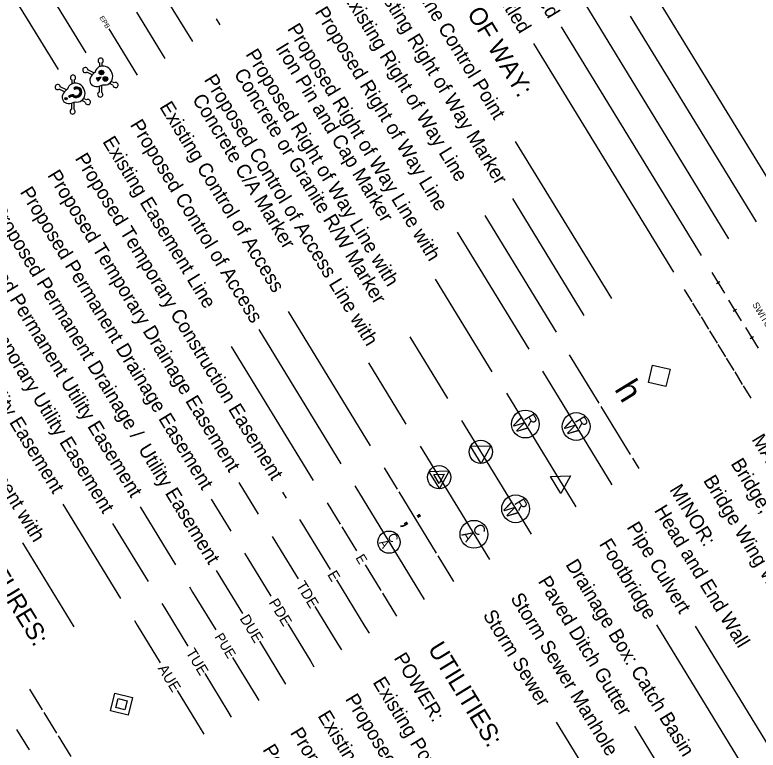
# Model space of a CAD drawing. Extents: x 1750583 to 1791140, y 783580 to 827376.
# Drawn here: x 1782646 to 1783106.5, y 784461.2 to 784917 of the extents above; entities that cross this region are included whole.
import ezdxf

# ---------------------------------------------------------------- set-up
doc = ezdxf.new("R2010")
doc.units = 0
for name, color, linetype in [('Prop Dimension Text', 7, 'Continuous'), ('Prop Easement Permanent Drainage Utility', 7, 'Continuous'), ('Prop ROW Permanent Easement CELL', 7, 'Continuous'), ('Sheet Symbology CELL', 7, 'Continuous')]:
    doc.layers.add(name, color=color, linetype=linetype)

msp = doc.modelspace()

# ---------------------------------------------------------------- linework, layer by layer
at = {"layer": 'Prop Dimension Text'}
msp.add_lwpolyline([(1783041.18, 784699.91), (1783051.94, 784697.31), (1783049.34, 784686.56), (1783038.59, 784689.15)], close=True, dxfattribs=at)
at = {"layer": 'Prop Easement Permanent Drainage Utility'}
for p, q in [((1782770.72, 784572.53), (1782787.04, 784545.82)), ((1782797.47, 784528.76), (1782813.74, 784502.13))]:
    msp.add_line(p, q, dxfattribs=at)
at = {"layer": 'Prop ROW Permanent Easement CELL'}
msp.add_line((1782712.08, 784489.66), (1782712.08, 784489.66), dxfattribs=at)
for points in [[(1782718.95, 784493.86), (1782716.28, 784482.79), (1782705.21, 784485.46), (1782707.88, 784496.53)], [(1782715.51, 784491.76), (1782714.18, 784486.22), (1782708.64, 784487.56), (1782709.98, 784493.09)]]:
    msp.add_lwpolyline(points, close=True, dxfattribs=at)
at = {"layer": 'Sheet Symbology CELL'}
for p, q in [((1783088.43, 784778.24), (1782976.37, 784961.63)), ((1782663.05, 784937.43), (1782689.87, 784893.54)), ((1783122.56, 784799.1), (1783039.96, 784934.28)), ((1782738, 784929.81), (1782755.95, 784900.44)), ((1782645.98, 784927), (1782672.8, 784883.11)), ((1782721.41, 784918.64), (1782738.89, 784890.02)), ((1783105.49, 784788.67), (1783027.52, 784916.29)), ((1782770.71, 784914.64), (1782773.02, 784910.87)), ((1782704.22, 784908.4), (1782721.83, 784879.59)), ((1783071.36, 784767.82), (1782984.72, 784909.61)), ((1783054.29, 784757.39), (1782967.66, 784899.18)), ((1783054.29, 784757.39), (1782967.66, 784899.18)), ((1782698.35, 784887.2), (1782698.32, 784884.8)), ((1782695, 784880.99), (1782691.24, 784882.85)), ((1782699.87, 784887.18), (1782699.85, 784885.23)), ((1782693.84, 784879.87), (1782690.57, 784881.5)), ((1782699, 784878.15), (1782699, 784878.15)), ((1782681.23, 784876.65), (1782681.2, 784874.24)), ((1782682.74, 784876.63), (1782682.72, 784874.68)), ((1782706.75, 784873.45), (1782704.6, 784874.52)), ((1782707.43, 784874.81), (1782705.69, 784875.68)), ((1782676.71, 784869.32), (1782673.44, 784870.94)), ((1782677.87, 784870.43), (1782674.11, 784872.3)), ((1782682.47, 784871.62), (1782682.97, 784870.8)), ((1782698.17, 784872.78), (1782698.13, 784869.12)), ((1782699.69, 784873.31), (1782699.64, 784869.11)), ((1782679.96, 784867), (1782679.24, 784866.55)), ((1782679.24, 784866.55), (1782679.74, 784865.73)), ((1782680.03, 784866.88), (1782679.31, 784866.44)), ((1782680.1, 784866.76), (1782679.38, 784866.32)), ((1782680.17, 784866.64), (1782679.45, 784866.2)), ((1782680.25, 784866.53), (1782679.52, 784866.08)), ((1782680.32, 784866.41), (1782679.6, 784865.97)), ((1782680.39, 784866.29), (1782679.67, 784865.85)), ((1782680.46, 784866.17), (1782679.74, 784865.73)), ((1782682.29, 784867.86), (1782682.29, 784867.86)), ((1782690.3, 784864.25), (1782688.56, 784865.12)), ((1782681.04, 784862.22), (1782681, 784858.57)), ((1782682.57, 784862.75), (1782682.51, 784858.55)), ((1782689.63, 784862.9), (1782687.47, 784863.97)), ((1783015.81, 784741.07), (1782956.26, 784838.53)), ((1782998.74, 784730.64), (1782954.46, 784803.12)), ((1782981.67, 784720.21), (1782937.39, 784792.69)), ((1782964.61, 784709.78), (1782920.32, 784782.26)), ((1783077.82, 784757.24), (1783085.64, 784744.44)), ((1782941.7, 784695.78), (1782906.7, 784753.05)), ((1783082.8, 784751.49), (1783080.66, 784750.19)), ((1783060.75, 784746.81), (1783065.45, 784739.13)), ((1783088.25, 784740.17), (1783096.07, 784727.37)), ((1783065.97, 784738.28), (1783070.66, 784730.6)), ((1782866.41, 784649.78), (1782815.55, 784733.03)), ((1783093.22, 784734.43), (1783091.09, 784733.12)), ((1783071.18, 784729.75), (1783075.87, 784722.07)), ((1782848.19, 784638.65), (1782797.33, 784721.89)), ((1783098.68, 784723.11), (1783106.5, 784710.31)), ((1782914.36, 784679.08), (1782890.9, 784717.47)), ((1783076.39, 784721.21), (1783081.09, 784713.53)), ((1783103.65, 784717.36), (1783101.52, 784716.06)), ((1783081.61, 784712.68), (1783086.3, 784705)), ((1782831.12, 784628.23), (1782780.26, 784711.47)), ((1782989.54, 784706.23), (1783007.79, 784676.37)), ((1783086.82, 784704.15), (1783091.51, 784696.47)), ((1782888.55, 784663.31), (1782865.29, 784701.38)), ((1782972.86, 784696.04), (1783015.87, 784625.64)), ((1783092.04, 784695.61), (1783096.73, 784687.93)), ((1783097.25, 784687.08), (1783101.94, 784679.4)), ((1782950.57, 784682.42), (1782993.58, 784612.02)), ((1783009.09, 784674.23), (1783027.34, 784644.37)), ((1782922.83, 784665.47), (1782965.85, 784595.07)), ((1782897.02, 784649.7), (1782940.04, 784579.3)), ((1782934.67, 784646.1), (1782934.67, 784646.1)), ((1783028.64, 784642.23), (1783032.56, 784635.83)), ((1782874.77, 784636.11), (1782882.83, 784622.91)), ((1782908.86, 784630.33), (1782908.86, 784630.33)), ((1782796.99, 784607.37), (1782784.92, 784627.12)), ((1782856.55, 784624.97), (1782899.56, 784554.57)), ((1782984.17, 784627.42), (1782984.17, 784627.42)), ((1782814.26, 784617.47), (1782812.08, 784621.03)), ((1782883.87, 784621.2), (1782907.03, 784583.31)), ((1782779.93, 784596.94), (1782767.86, 784616.7)), ((1782711.65, 784555.23), (1782675.96, 784613.64)), ((1782745.78, 784576.08), (1782723.82, 784612.04)), ((1782839.48, 784614.55), (1782847.57, 784601.31)), ((1782822.42, 784604.12), (1782823.78, 784601.89)), ((1782823.78, 784601.89), (1782841.37, 784573.09)), ((1782728.72, 784565.65), (1782706.75, 784601.61)), ((1782848.61, 784599.6), (1782857.74, 784584.67)), ((1782805.35, 784593.69), (1782807.1, 784590.83)), ((1782682.79, 784537.59), (1782650.98, 784589.65)), ((1782807.1, 784590.83), (1782821.43, 784567.37)), ((1782788.28, 784583.26), (1782790.26, 784580.02)), ((1782790.26, 784580.02), (1782804.6, 784556.55)), ((1782908.07, 784581.6), (1782917.78, 784565.71)), ((1782862.95, 784576.14), (1782872.73, 784560.14)), ((1782845.29, 784566.69), (1782862.88, 784537.89)), ((1782754.14, 784562.4), (1782756.14, 784559.13)), ((1782756.14, 784559.13), (1782770.48, 784535.66)), ((1782873.77, 784558.43), (1782882.5, 784544.15)), ((1782737.08, 784551.98), (1782738.82, 784549.12)), ((1782738.82, 784549.12), (1782753.16, 784525.65)), ((1782831.86, 784550.3), (1782846.2, 784526.83)), ((1782720.01, 784541.55), (1782721.76, 784538.69)), ((1782721.76, 784538.69), (1782736.09, 784515.22)), ((1782815.03, 784539.49), (1782829.37, 784516.02)), ((1782862.88, 784537.89), (1782865.43, 784533.72)), ((1783139.36, 784382.32), (1783043.7, 784538.88)), ((1783156.43, 784392.75), (1783067.69, 784537.97)), ((1782846.2, 784526.83), (1782848.36, 784523.29)), ((1782780.91, 784518.6), (1782795.25, 784495.13)), ((1782829.37, 784516.02), (1782831.3, 784512.86)), ((1782763.59, 784508.58), (1782777.93, 784485.12)), ((1782655.13, 784498.98), (1782662.95, 784486.18)), ((1782746.52, 784498.16), (1782760.86, 784474.69)), ((1782795.25, 784495.13), (1782797.16, 784492)), ((1782664, 784484.47), (1782671.82, 784471.67)), ((1782777.93, 784485.12), (1782780.09, 784481.58)), ((1783067.31, 784338.3), (1782981.7, 784478.42)), ((1782646.93, 784474.05), (1782654.75, 784461.25)), ((1782760.86, 784474.69), (1782763.02, 784471.15)), ((1783101.45, 784359.15), (1783030.04, 784476.02)), ((1782672.86, 784469.97), (1782680.68, 784457.17))]:
    msp.add_line(p, q, dxfattribs=at)
for points in [[(1782699.42, 784878.41), (1782696.38, 784877.8), (1782697.49, 784875.98)], [(1782699, 784878.15), (1782696.65, 784877.68), (1782697.51, 784876.28)], [(1782698.58, 784877.9), (1782696.92, 784877.56), (1782697.53, 784876.58)], [(1782698.15, 784877.64), (1782697.2, 784877.45), (1782697.55, 784876.87)], [(1782697.73, 784877.38), (1782697.47, 784877.33), (1782697.56, 784877.17)], [(1782928.34, 784649.56), (1782940.81, 784649.86), (1782934.85, 784638.89)], [(1782902.53, 784633.79), (1782909.05, 784623.12), (1782915, 784634.09)], [(1782905.55, 784632.14), (1782912.07, 784632.3), (1782908.96, 784626.56)], [(1782977.84, 784630.88), (1782990.31, 784631.18), (1782984.36, 784620.21)]]:
    msp.add_lwpolyline(points, close=True, dxfattribs=at)
for centre, radius in [((1782699.61, 784881.27), 1.44), ((1782699.61, 784881.27), 1.27), ((1782699.61, 784881.27), 1.1), ((1782699.61, 784881.27), 0.932), ((1782699.61, 784881.27), 0.762), ((1782699.61, 784881.27), 0.592), ((1782699.61, 784881.27), 0.422), ((1782699.61, 784881.27), 0.252), ((1782699.61, 784881.27), 0.0815), ((1782702.05, 784877.27), 1.44), ((1782702.05, 784877.27), 1.27), ((1782702.05, 784877.27), 1.1), ((1782702.05, 784877.27), 0.932), ((1782702.05, 784877.27), 0.762), ((1782702.05, 784877.27), 0.592), ((1782702.05, 784877.27), 0.422), ((1782702.05, 784877.27), 0.252), ((1782702.05, 784877.27), 0.0815), ((1782677.72, 784865.02), 0.689), ((1782677.72, 784865.02), 0.536), ((1782677.72, 784865.02), 0.379), ((1782677.72, 784865.02), 0.226), ((1782677.72, 784865.02), 0.0734), ((1782962.26, 784663.29), 8.61), ((1782993.78, 784661.8), 8.61), ((1782934.66, 784646.1), 7.2), ((1782908.86, 784630.33), 7.2), ((1782956.25, 784610.78), 8.61), ((1782930.44, 784595.01), 8.61), ((1782877.86, 784590.09), 6.89)]:
    msp.add_circle(centre, radius, dxfattribs=at)
for centre, start, end in [((1782699.13, 784888.61), 297.3226, 241.2311), ((1782689.63, 784882.81), 1.6188, 305.5273), ((1782682, 784878.06), 297.3226, 241.2311), ((1782672.5, 784872.25), 1.6188, 305.5273), ((1782708.37, 784873.5), 181.6188, 125.5273), ((1782698.87, 784867.69), 117.3226, 61.2311), ((1782691.24, 784862.94), 181.6188, 125.5273), ((1782681.74, 784857.14), 117.3226, 61.2311)]:
    msp.add_arc(centre, 1.61, start, end, dxfattribs=at)
for centre, major_axis, ratio, start_param, end_param in [((1782701.05, 784879.41), (3.15, -5.16), 0.885014, 5.564242, 10.143721), ((1782698.1, 784877.6), (-5.16, -3.15), 0.752542, 4.722735, 7.843636), ((1782683.92, 784868.85), (3.15, -5.16), 0.885014, 5.564242, 10.143721), ((1782680.97, 784867.05), (-5.16, -3.15), 0.752542, 4.722735, 7.843636), ((1782684.09, 784868.96), (2.96, 1.81), 0.9, 3.567618, 7.853982), ((1782684.09, 784868.96), (2.83, 1.73), 0.9, 3.567618, 7.853982), ((1782684.09, 784868.96), (2.7, 1.65), 0.9, 3.567618, 7.853982), ((1782684.09, 784868.96), (2.57, 1.57), 0.9, 3.567618, 7.853982), ((1782684.09, 784868.96), (2.44, 1.49), 0.9, 3.567618, 7.853982), ((1782684.09, 784868.96), (2.31, 1.41), 0.9, 3.567618, 7.853982), ((1782684.09, 784868.96), (2.18, 1.33), 0.9, 3.567618, 7.853982), ((1782684.09, 784868.96), (2.05, 1.25), 0.9, 3.567618, 7.853982), ((1782681.18, 784865), (2.22, 1.36), 0.9, 0.426026, 1.570796), ((1782681.18, 784865), (2.09, 1.28), 0.9, 0.426026, 1.570796), ((1782681.18, 784865), (1.96, 1.2), 0.9, 0.426026, 1.570796), ((1782681.18, 784865), (1.83, 1.12), 0.9, 0.426026, 1.570796), ((1782681.18, 784865), (1.7, 1.04), 0.9, 0.426026, 1.570796), ((1782681.18, 784865), (1.57, 0.96), 0.9, 0.426026, 1.570796), ((1782681.18, 784865), (1.44, 0.88), 0.9, 0.426026, 1.570796), ((1782681.18, 784865), (1.31, 0.8), 0.9, 0.426026, 1.570796)]:
    msp.add_ellipse(centre, major_axis=major_axis, ratio=ratio, start_param=start_param, end_param=end_param, dxfattribs=at)

# ---------------------------------------------------------------- texts
at = {"layer": 'Prop Easement Permanent Drainage Utility'}
msp.add_text('DUE', height=6.55, rotation=301.4249, dxfattribs=at).set_placement((1782785.05, 784542.75))
at = {"layer": 'Sheet Symbology CELL'}
for s, height, p in [('CONVENTIONAL  PLAN SHEET SYMBOLS', 27.2003, (1783052.38, 785044.06)), ('RR Abandoned', 8.75, (1782934.98, 784982.34)), ('RR Dismantled', 8.75, (1782917.92, 784971.91)), ('RIGHT OF WAY:', 11, (1782899.82, 784960.53)), ('Baseline Control Point', 8.75, (1782882.75, 784950.1)), ('Existing Right of Way Marker', 8.75, (1782865.69, 784939.68)), ('Existing Right of Way Line', 8.75, (1782848.62, 784929.25)), ('Proposed Right of Way Line', 8.75, (1782831.55, 784918.82)), ('EPB', 3, (1782698.25, 784915.3)), ('Proposed Right of Way Line with', 8.75, (1782814.49, 784908.39)), ('  Iron Pin and Cap Marker', 8.75, (1782803.82, 784901.88)), ('Proposed Right of Way Line with', 8.75, (1782788.69, 784892.64)), ('  Concrete or Granite R/W Marker', 8.75, (1782778.03, 784886.12)), ('Proposed Control of Access Line with', 8.75, (1782762.89, 784876.87)), ('  Concrete C/A Marker', 8.75, (1782752.22, 784870.35)), ('Existing Control of Access', 8.75, (1782735.31, 784860.02)), ('Proposed Control of Access', 8.75, (1782717.09, 784848.88)), ('Existing Easement Line', 8.75, (1782700.02, 784838.46)), ('Proposed Temporary Construction Easement', 8.75, (1782682.96, 784828.03)), ('Proposed Temporary Drainage Easement', 8.75, (1782665.89, 784817.6)), ('Proposed Permanent Drainage Easement', 8.75, (1782648.82, 784807.17)), ('Proposed Permanent Drainage /  Utility Easement', 8.75, (1782631.26, 784796.44)), ('Proposed Permanent Utility Easement', 8.75, (1782614.68, 784786.31)), ('Proposed Temporary Utility Easement', 8.75, (1782597.62, 784775.89)), ('Proposed Aerial Utility Easement', 8.75, (1782580.55, 784765.46)), ('Proposed Permanent Easement with', 8.75, (1782558.48, 784751.98)), ('ROADS AND RELATED FEATURES:', 11, (1782529.97, 784734.56)), ('SWITCH', 4, (1783102.78, 784737.39)), ('h', 15, (1783017.16, 784685.01)), ('W', 6.75, (1782953.6, 784664.15)), ('R', 6.75, (1782961.19, 784666.98)), ('W', 6.75, (1782985.12, 784662.66)), ('R', 6.75, (1782992.71, 784665.5)), ('MAJOR:', 8.75, (1783102.28, 784653.8)), ('Bridge, Tunnel or Box Culvert', 8.75, (1783089.31, 784638.81)), ('Bridge Wing Wall, Head Wall and End Wall', 8.75, (1783072.24, 784628.38)), ('MINOR:', 8.75, (1783051.34, 784622.67)), ('R', 6.75, (1782955.18, 784614.47)), ('W', 6.75, (1782947.6, 784611.64)), ('Head and End Wall', 8.75, (1783041.89, 784609.84)), (';', 15, (1782885.96, 784603.4)), ('Pipe Culvert', 8.75, (1783024.83, 784599.41)), ('C', 6.75, (1782929.24, 784598.92)), ('C', 5.4, (1782876.64, 784593.64)), ('A', 6.75, (1782922.42, 784594.83)), ('Footbridge', 8.75, (1783007.77, 784588.98)), ('A', 5.4, (1782871.39, 784589.8)), ('E', 6, (1782856.85, 784580.37)), ('Drainage Box: Catch Basin, DI or JB', 8.75, (1782986.93, 784576.24)), ('E', 6.55, (1782839.39, 784570)), ('Paved Ditch Gutter', 8.75, (1782969.85, 784565.8)), ('TDE', 6.55, (1782819.97, 784563.43)), ('Storm Sewer Manhole', 8.75, (1782952.78, 784555.38)), ('PDE', 6.55, (1782803.09, 784552.7)), ('Storm Sewer', 8.75, (1782935.72, 784544.95)), ('PUE', 6, (1782769.54, 784531.45)), ('UTILITIES:', 11, (1782901.58, 784524.1)), ('TUE', 6.55, (1782751.69, 784521.73)), ('POWER:', 8.75, (1782880.53, 784518.3)), ('AUE', 6.55, (1782734.28, 784511.86)), ('Existing Power Pole', 8.75, (1782867.46, 784503.25)), ('Proposed Power Pole', 8.75, (1782850.4, 784492.82)), ('Existing Joint Use Pole', 8.75, (1782833.34, 784482.4)), ('Proposed Joint Use Pole', 8.75, (1782816.27, 784471.95)), ('Power Manhole', 8.75, (1782799.2, 784461.52))]:
    msp.add_text(s, height=height, rotation=301.4249, dxfattribs=at).set_placement(p)

doc.saveas('drawing.dxf')
